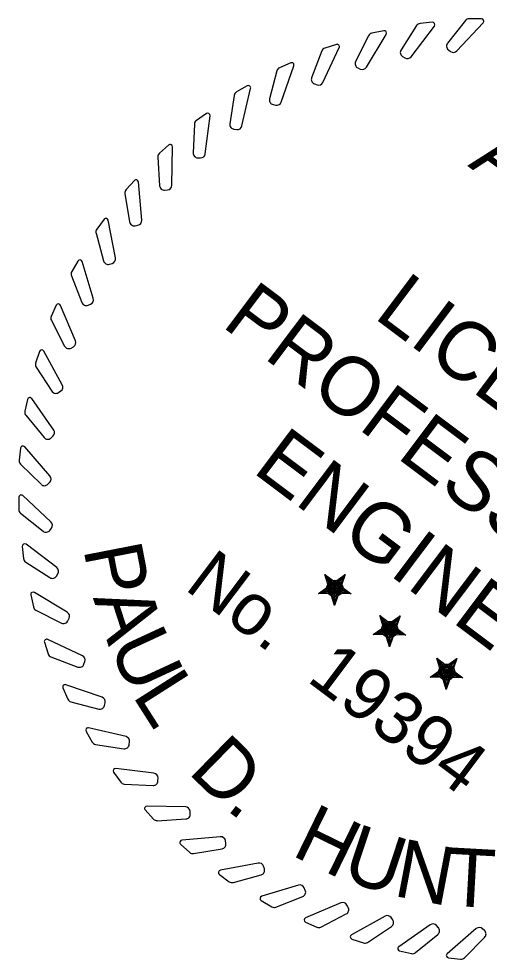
# Model space of a CAD drawing. Extents: x 627721 to 628787, y 367711 to 368404.
# Drawn here: x 628713.7 to 628750.3, y 368170.5 to 368243.5 of the extents above; entities that cross this region are included whole.
import ezdxf

# ---------------------------------------------------------------- set-up
doc = ezdxf.new("R2010")
doc.units = 0
doc.layers.add('R_Border PE-PDH', color=7, linetype='Continuous')

msp = doc.modelspace()

# ---------------------------------------------------------------- linework, layer by layer
at = {"layer": 'R_Border PE-PDH'}
for p, q in [((628737.497, 368200.397), (628738.272, 368199.309)), ((628737.497, 368200.397), (628738.136, 368199.712)), ((628737.497, 368200.397), (628737.921, 368199.522)), ((628738.272, 368199.309), (628739.071, 368200.373)), ((628739.071, 368200.373), (628738.4, 368199.728)), ((628739.071, 368200.373), (628738.666, 368199.537)), ((628736.992, 368198.916), (628737.893, 368199.352)), ((628736.992, 368198.916), (628738.272, 368199.309)), ((628738.243, 368197.977), (628738.272, 368199.309)), ((628739.526, 368198.873), (628738.272, 368199.309)), ((628739.526, 368198.873), (628738.585, 368199.357)), ((628736.992, 368198.916), (628738.091, 368199.081)), ((628738.243, 368197.977), (628738.084, 368199.072)), ((628738.243, 368197.977), (628738.48, 368199.125)), ((628739.526, 368198.873), (628738.708, 368199.023)), ((628741.757, 368197.198), (628742.532, 368196.111)), ((628741.757, 368197.198), (628742.396, 368196.513)), ((628741.757, 368197.198), (628742.181, 368196.324)), ((628742.532, 368196.111), (628743.331, 368197.175)), ((628743.331, 368197.175), (628742.66, 368196.53)), ((628743.331, 368197.175), (628742.926, 368196.339)), ((628741.252, 368195.718), (628742.153, 368196.153)), ((628741.252, 368195.718), (628742.532, 368196.111)), ((628741.252, 368195.718), (628742.351, 368195.882)), ((628742.503, 368194.779), (628742.344, 368195.873)), ((628742.503, 368194.779), (628742.532, 368196.111)), ((628742.503, 368194.779), (628742.74, 368195.927)), ((628743.786, 368195.675), (628742.532, 368196.111)), ((628743.786, 368195.675), (628742.845, 368196.158)), ((628743.786, 368195.675), (628742.968, 368195.824)), ((628746.175, 368193.881), (628746.95, 368192.793)), ((628746.175, 368193.881), (628746.814, 368193.196)), ((628746.175, 368193.881), (628746.599, 368193.006)), ((628746.95, 368192.793), (628747.749, 368193.857)), ((628747.749, 368193.857), (628747.077, 368193.212)), ((628747.749, 368193.857), (628747.344, 368193.021)), ((628745.67, 368192.4), (628746.571, 368192.836)), ((628745.67, 368192.4), (628746.95, 368192.793)), ((628746.92, 368191.461), (628746.95, 368192.793)), ((628746.92, 368191.461), (628747.158, 368192.609)), ((628748.204, 368192.357), (628746.95, 368192.793)), ((628748.204, 368192.357), (628747.263, 368192.84)), ((628745.67, 368192.4), (628746.769, 368192.564)), ((628746.92, 368191.461), (628746.762, 368192.556)), ((628748.204, 368192.357), (628747.386, 368192.506))]:
    msp.add_line(p, q, dxfattribs=at)
for points in [[(628744.614, 368243.014), (628743.411, 368241.135)], [(628745.833, 368243.273), (628744.887, 368243.18)], [(628748.409, 368243.408), (628747.016, 368241.665)], [(628747.741, 368241.055), (628749.78, 368243.231)], [(628749.648, 368243.539), (628748.697, 368243.546)], [(628740.718, 368239.784), (628742.26, 368242.336)], [(628742.067, 368242.61), (628741.135, 368242.419)], [(628744.196, 368240.604), (628745.997, 368242.981)], [(628738.39, 368241.557), (628737.484, 368241.269)], [(628740.882, 368242.224), (628739.882, 368240.23)], [(628737.252, 368241.049), (628736.466, 368238.961)], [(628737.344, 368238.605), (628738.611, 368241.305)], [(628747.08, 368241.146), (628747.252, 368241.014)], [(628734.844, 368240.125), (628733.973, 368239.744)], [(628743.529, 368240.624), (628743.715, 368240.512)], [(628733.766, 368239.501), (628733.202, 368237.342)], [(628734.112, 368237.08), (628735.09, 368239.897)], [(628740.053, 368239.735), (628740.248, 368239.642)], [(628731.467, 368238.33), (628730.641, 368237.861)], [(628731.058, 368235.226), (628731.736, 368238.13)], [(628736.688, 368238.487), (628736.892, 368238.415)], [(628730.46, 368237.597), (628730.125, 368235.391)], [(628733.472, 368236.894), (628733.683, 368236.844)], [(628728.296, 368236.192), (628727.523, 368235.639)], [(628728.214, 368233.062), (628728.584, 368236.021)], [(628727.371, 368235.358), (628727.268, 368233.129)], [(628730.44, 368234.973), (628730.655, 368234.946)], [(628725.366, 368233.735), (628724.655, 368233.104)], [(628725.611, 368230.613), (628725.671, 368233.594)], [(628724.533, 368232.809), (628724.664, 368230.581)], [(628727.626, 368232.747), (628727.842, 368232.742)], [(628722.709, 368230.985), (628722.068, 368230.282)], [(628723.279, 368227.905), (628723.026, 368230.877)], [(628721.977, 368229.976), (628722.34, 368227.775)], [(628725.059, 368230.238), (628725.275, 368230.256)], [(628720.354, 368227.971), (628719.79, 368227.206)], [(628721.243, 368224.969), (628720.681, 368227.897)], [(628722.77, 368227.475), (628722.982, 368227.515)], [(628719.732, 368226.892), (628720.323, 368224.741)], [(628718.327, 368224.729), (628717.846, 368223.909)], [(628719.524, 368221.835), (628718.66, 368224.689)], [(628720.781, 368224.487), (628720.989, 368224.549)], [(628717.821, 368223.59), (628718.633, 368221.512)], [(628716.649, 368221.292), (628716.257, 368220.426)], [(628718.143, 368218.54), (628716.985, 368221.287)], [(628719.116, 368221.308), (628719.315, 368221.392)], [(628716.265, 368220.107), (628717.291, 368218.125)], [(628715.341, 368217.699), (628715.041, 368216.796)], [(628717.114, 368215.117), (628715.675, 368217.729)], [(628717.792, 368217.972), (628717.982, 368218.077)], [(628715.082, 368216.48), (628716.31, 368214.616)], [(628716.824, 368214.517), (628717.002, 368214.64)], [(628714.415, 368213.988), (628714.211, 368213.06)], [(628716.448, 368211.606), (628714.744, 368214.053)], [(628714.285, 368212.749), (628715.7, 368211.024)], [(628716.222, 368210.979), (628716.386, 368211.12)], [(628713.882, 368210.201), (628713.776, 368209.256)], [(628716.153, 368208.045), (628714.202, 368210.3)], [(628713.882, 368208.955), (628715.47, 368207.388)], [(628715.994, 368207.397), (628716.142, 368207.555)], [(628716.231, 368204.472), (628714.055, 368206.511)], [(628713.747, 368206.379), (628713.741, 368205.429)], [(628713.878, 368205.14), (628715.621, 368203.747)], [(628716.141, 368203.811), (628716.272, 368203.984)], [(628714.013, 368202.564), (628714.106, 368201.618)], [(628716.683, 368200.927), (628714.306, 368202.728)], [(628714.273, 368201.346), (628716.152, 368200.142)], [(628716.662, 368200.261), (628716.775, 368200.446)], [(628739.071, 368200.373), (628738.243, 368197.977), (628737.497, 368200.397), (628739.526, 368198.873), (628736.992, 368198.916), (628739.071, 368200.373)], [(628714.677, 368198.798), (628714.868, 368197.867)], [(628717.503, 368197.449), (628714.95, 368198.991)], [(628715.062, 368197.613), (628717.057, 368196.613)], [(628743.331, 368197.175), (628742.503, 368194.779), (628741.757, 368197.198), (628743.786, 368195.675), (628741.252, 368195.718), (628743.331, 368197.175)], [(628717.552, 368196.784), (628717.644, 368196.98)], [(628715.73, 368195.122), (628716.017, 368194.215)], [(628718.681, 368194.076), (628715.982, 368195.342)], [(628716.237, 368193.984), (628718.326, 368193.197)], [(628718.8, 368193.419), (628718.871, 368193.623)], [(628747.749, 368193.857), (628746.92, 368191.461), (628746.175, 368193.881), (628748.204, 368192.357), (628745.67, 368192.4), (628747.749, 368193.857)], [(628717.162, 368191.575), (628717.542, 368190.704)], [(628720.206, 368190.844), (628717.389, 368191.822)], [(628717.785, 368190.497), (628719.944, 368189.933)], [(628720.393, 368190.203), (628720.443, 368190.414)], [(628722.061, 368187.789), (628719.157, 368188.467)], [(628718.956, 368188.198), (628719.426, 368187.372)], [(628719.689, 368187.191), (628721.895, 368186.856)], [(628722.313, 368187.171), (628722.341, 368187.386)], [(628724.225, 368184.945), (628721.266, 368185.316)], [(628721.094, 368185.027), (628721.648, 368184.255)], [(628724.54, 368184.357), (628724.545, 368184.574)], [(628721.928, 368184.102), (628724.157, 368184)], [(628726.674, 368182.342), (628723.692, 368182.402)], [(628723.552, 368182.097), (628724.183, 368181.387)], [(628727.049, 368181.791), (628727.031, 368182.007)], [(628724.478, 368181.264), (628726.706, 368181.395)], [(628729.381, 368180.01), (628726.41, 368179.758)], [(628729.812, 368179.501), (628729.772, 368179.714)], [(628726.302, 368179.44), (628727.004, 368178.799)], [(628727.311, 368178.708), (628729.512, 368179.072)], [(628732.318, 368177.974), (628729.389, 368177.412)], [(628732.8, 368177.512), (628732.737, 368177.72)], [(628729.315, 368177.085), (628730.08, 368176.521)], [(628730.395, 368176.463), (628732.546, 368177.054)], [(628735.451, 368176.256), (628732.597, 368175.391)], [(628735.979, 368175.847), (628735.895, 368176.047)], [(628733.696, 368174.552), (628735.774, 368175.365)], [(628732.558, 368175.058), (628733.378, 368174.577)], [(628738.747, 368174.874), (628735.999, 368173.716)], [(628739.314, 368174.523), (628739.21, 368174.713)], [(628737.18, 368172.996), (628739.162, 368174.022)], [(628742.169, 368173.845), (628739.558, 368172.406)], [(628742.77, 368173.555), (628742.647, 368173.733)], [(628735.995, 368173.381), (628736.861, 368172.988)], [(628740.807, 368171.814), (628742.671, 368173.041)], [(628745.68, 368173.179), (628743.233, 368171.475)], [(628746.308, 368172.953), (628746.167, 368173.118)], [(628744.538, 368171.016), (628746.263, 368172.432)], [(628749.242, 368172.884), (628746.986, 368170.933)], [(628748.331, 368170.614), (628749.899, 368172.201)], [(628749.89, 368172.725), (628749.732, 368172.873)], [(628739.588, 368172.072), (628740.49, 368171.772)], [(628743.299, 368171.146), (628744.227, 368170.942)], [(628747.086, 368170.613), (628748.03, 368170.507)]]:
    msp.add_lwpolyline(points, dxfattribs=at)
for centre, radius in [((628738.267, 368199.309), 0.628), ((628738.267, 368199.309), 0.527), ((628738.267, 368199.309), 0.422), ((628738.267, 368199.309), 0.361), ((628738.267, 368199.309), 0.272), ((628738.267, 368199.309), 0.181), ((628738.267, 368199.309), 0.108), ((628742.527, 368196.11), 0.628), ((628742.527, 368196.11), 0.527), ((628742.527, 368196.11), 0.422), ((628742.527, 368196.11), 0.361), ((628742.527, 368196.11), 0.272), ((628742.527, 368196.11), 0.181), ((628742.527, 368196.11), 0.108), ((628746.945, 368192.793), 0.628), ((628746.945, 368192.793), 0.527), ((628746.945, 368192.793), 0.422), ((628746.945, 368192.793), 0.361), ((628746.945, 368192.793), 0.272), ((628746.945, 368192.793), 0.181), ((628746.945, 368192.793), 0.108)]:
    msp.add_circle(centre, radius, dxfattribs=at)
for centre, radius, start, end in [((628744.923, 368242.816), 0.366, 95.60902, 147.36527), ((628745.851, 368243.091), 0.183, 322.85775, 95.60902), ((628748.695, 368243.18), 0.366, 89.60902, 141.36527), ((628749.647, 368243.356), 0.183, 316.85775, 89.60902), ((628741.209, 368242.06), 0.366, 101.60902, 153.36527), ((628742.103, 368242.431), 0.183, 328.85775, 101.60902), ((628738.446, 368241.382), 0.183, 334.85775, 107.60902), ((628747.302, 368241.437), 0.366, 141.36527, 232.72305), ((628737.595, 368240.92), 0.366, 107.60902, 159.36527), ((628743.719, 368240.937), 0.366, 147.36527, 238.72305), ((628747.474, 368241.306), 0.366, 232.72305, 316.85775), ((628734.917, 368239.957), 0.183, 340.85775, 113.60902), ((628740.209, 368240.066), 0.366, 153.36527, 244.72305), ((628743.904, 368240.825), 0.366, 238.72305, 322.85775), ((628734.12, 368239.409), 0.366, 113.60902, 165.36527), ((628740.405, 368239.973), 0.366, 244.72305, 328.85775), ((628736.809, 368238.832), 0.366, 159.36527, 250.72305), ((628731.558, 368238.171), 0.183, 346.85775, 119.60902), ((628737.013, 368238.761), 0.366, 250.72305, 334.85775), ((628730.821, 368237.542), 0.366, 119.60902, 171.36527), ((628733.556, 368237.25), 0.366, 165.36527, 256.72305), ((628733.767, 368237.2), 0.366, 256.72305, 340.85775), ((628728.403, 368236.044), 0.183, 352.85775, 125.60902), ((628727.736, 368235.341), 0.366, 125.60902, 177.36527), ((628730.486, 368235.336), 0.366, 171.36527, 262.72305), ((628730.701, 368235.309), 0.366, 262.72305, 346.85775), ((628725.488, 368233.598), 0.183, 358.85775, 131.60902), ((628724.898, 368232.83), 0.366, 131.60902, 183.36527), ((628727.634, 368233.112), 0.366, 177.36527, 268.72305), ((628727.85, 368233.108), 0.366, 268.72305, 352.85775), ((628722.844, 368230.861), 0.183, 4.85775, 137.60902), ((628725.245, 368230.62), 0.366, 274.72305, 358.85775), ((628722.338, 368230.036), 0.366, 137.60902, 189.36527), ((628725.029, 368230.603), 0.366, 183.36527, 274.72305), ((628720.501, 368227.863), 0.183, 10.85775, 143.60902), ((628722.701, 368227.834), 0.366, 189.36527, 280.72305), ((628722.914, 368227.874), 0.366, 280.72305, 4.85775), ((628720.084, 368226.989), 0.366, 143.60902, 195.36527), ((628718.484, 368224.636), 0.183, 16.85775, 149.60902), ((628720.883, 368224.9), 0.366, 286.72305, 10.85775), ((628720.676, 368224.838), 0.366, 195.36527, 286.72305), ((628718.161, 368223.724), 0.366, 149.60902, 201.36527), ((628719.174, 368221.729), 0.366, 292.72305, 16.85775), ((628716.816, 368221.216), 0.183, 22.85775, 155.60902), ((628718.974, 368221.646), 0.366, 201.36527, 292.72305), ((628716.59, 368220.275), 0.366, 155.60902, 207.36527), ((628717.806, 368218.397), 0.366, 298.72305, 22.85775), ((628715.514, 368217.641), 0.183, 28.85775, 161.60902), ((628717.616, 368218.293), 0.366, 207.36527, 298.72305), ((628715.388, 368216.681), 0.366, 161.60902, 213.36527), ((628716.615, 368214.817), 0.366, 213.36527, 304.72305), ((628716.793, 368214.941), 0.366, 304.72305, 28.85775), ((628714.593, 368213.949), 0.183, 34.85775, 167.60902), ((628714.568, 368212.981), 0.366, 167.60902, 219.36527), ((628716.148, 368211.397), 0.366, 310.72305, 34.85775), ((628715.983, 368211.256), 0.366, 219.36527, 310.72305), ((628714.063, 368210.181), 0.183, 40.85775, 173.60902), ((628714.139, 368209.216), 0.366, 173.60902, 225.36527), ((628715.876, 368207.806), 0.366, 316.72305, 40.85775), ((628715.727, 368207.648), 0.366, 225.36527, 316.72305), ((628713.93, 368206.378), 0.183, 46.85775, 179.60902), ((628714.107, 368205.426), 0.366, 179.60902, 231.36527), ((628715.981, 368204.205), 0.366, 322.72305, 46.85775), ((628715.85, 368204.033), 0.366, 231.36527, 322.72305), ((628714.195, 368202.582), 0.183, 52.85775, 185.60902), ((628714.47, 368201.654), 0.366, 185.60902, 237.36527), ((628716.462, 368200.636), 0.366, 328.72305, 52.85775), ((628716.349, 368200.451), 0.366, 237.36527, 328.72305), ((628714.856, 368198.835), 0.183, 58.85775, 191.60902), ((628715.226, 368197.94), 0.366, 191.60902, 243.36527), ((628717.313, 368197.136), 0.366, 334.72305, 58.85775), ((628717.221, 368196.94), 0.366, 243.36527, 334.72305), ((628715.904, 368195.177), 0.183, 64.85775, 197.60902), ((628716.366, 368194.326), 0.366, 197.60902, 249.36527), ((628718.526, 368193.744), 0.366, 340.72305, 64.85775), ((628718.454, 368193.54), 0.366, 249.36527, 340.72305), ((628717.329, 368191.649), 0.183, 70.85775, 203.60902), ((628717.878, 368190.851), 0.366, 203.60902, 255.36527), ((628720.086, 368190.498), 0.366, 346.72305, 70.85775), ((628720.037, 368190.287), 0.366, 255.36527, 346.72305), ((628719.115, 368188.289), 0.183, 76.85775, 209.60902), ((628721.978, 368187.433), 0.366, 352.72305, 76.85775), ((628719.744, 368187.553), 0.366, 209.60902, 261.36527), ((628721.95, 368187.218), 0.366, 261.36527, 352.72305), ((628721.243, 368185.134), 0.183, 82.85775, 215.60902), ((628724.179, 368184.582), 0.366, 358.72305, 82.85775), ((628721.945, 368184.468), 0.366, 215.60902, 267.36527), ((628724.174, 368184.365), 0.366, 267.36527, 358.72305), ((628723.689, 368182.219), 0.183, 88.85775, 221.60902), ((628726.666, 368181.976), 0.366, 4.72305, 88.85775), ((628726.684, 368181.761), 0.366, 273.36527, 4.72305), ((628724.457, 368181.63), 0.366, 221.60902, 273.36527), ((628726.426, 368179.575), 0.183, 94.85775, 227.60902), ((628729.412, 368179.646), 0.366, 10.72305, 94.85775), ((628729.453, 368179.433), 0.366, 279.36527, 10.72305), ((628727.251, 368179.07), 0.366, 227.60902, 279.36527), ((628729.424, 368177.232), 0.183, 100.85775, 233.60902), ((628732.387, 368177.614), 0.366, 16.72305, 100.85775), ((628732.449, 368177.407), 0.366, 285.36527, 16.72305), ((628730.298, 368176.816), 0.366, 233.60902, 285.36527), ((628735.557, 368175.905), 0.366, 22.72305, 106.85775), ((628735.641, 368175.705), 0.366, 291.36527, 22.72305), ((628732.651, 368175.216), 0.183, 106.85775, 239.60902), ((628733.563, 368174.893), 0.366, 239.60902, 291.36527), ((628738.889, 368174.537), 0.366, 28.72305, 112.85775), ((628738.993, 368174.347), 0.366, 297.36527, 28.72305), ((628736.07, 368173.547), 0.183, 112.85775, 245.60902), ((628742.346, 368173.524), 0.366, 34.72305, 118.85775), ((628737.012, 368173.321), 0.366, 245.60902, 297.36527), ((628742.469, 368173.346), 0.366, 303.36527, 34.72305), ((628745.889, 368172.879), 0.366, 40.72305, 124.85775), ((628746.031, 368172.715), 0.366, 309.36527, 40.72305), ((628749.481, 368172.607), 0.366, 46.72305, 130.85775), ((628739.646, 368172.246), 0.183, 118.85775, 251.60902), ((628749.639, 368172.459), 0.366, 315.36527, 46.72305), ((628740.606, 368172.119), 0.366, 251.60902, 303.36527), ((628743.338, 368171.325), 0.183, 124.85775, 257.60902), ((628744.306, 368171.299), 0.366, 257.60902, 309.36527), ((628747.106, 368170.795), 0.183, 130.85775, 263.60902), ((628748.071, 368170.871), 0.366, 263.60902, 315.36527)]:
    msp.add_arc(centre, radius, start, end, dxfattribs=at)

# ---------------------------------------------------------------- texts
for s, height, rotation, p in [('ARKANSAS', 4.3912, 323.09683, (628748.536, 368232.134)), ('LICENSED', 4.5741, 323.09683, (628741.206, 368220.378)), ('PROFESSIONAL', 4.57414, 323.09683, (628729.399, 368219.71)), ('ENGINEER', 4.5741, 323.09683, (628731.789, 368208.382)), ('P', 4.526, 281.03267, (628718.74, 368202.387)), ('No.', 4.0534, 323.09683, (628726.515, 368199.288)), ('A', 4.526, 287.95523, (628719.483, 368198.575)), ('U', 4.526, 294.87779, (628720.681, 368194.879)), ('19394', 4.0534, 323.09683, (628735.999, 368192.166)), ('L', 4.526, 302.49261, (628722.502, 368191.014)), ('D', 4.526, 315.64547, (628726.793, 368185.024)), ('.', 4.526, 322.91416, (628729.718, 368182.182)), ('H', 4.526, 333.99026, (628734.804, 368178.62)), ('U', 4.526, 341.60507, (628738.655, 368176.77)), ('N', 4.526, 349.21989, (628742.717, 368175.446)), ('T', 4.526, 356.83471, (628746.919, 368174.673))]:
    msp.add_text(s, height=height, rotation=rotation, dxfattribs=at).set_placement(p)

doc.saveas('drawing.dxf')
